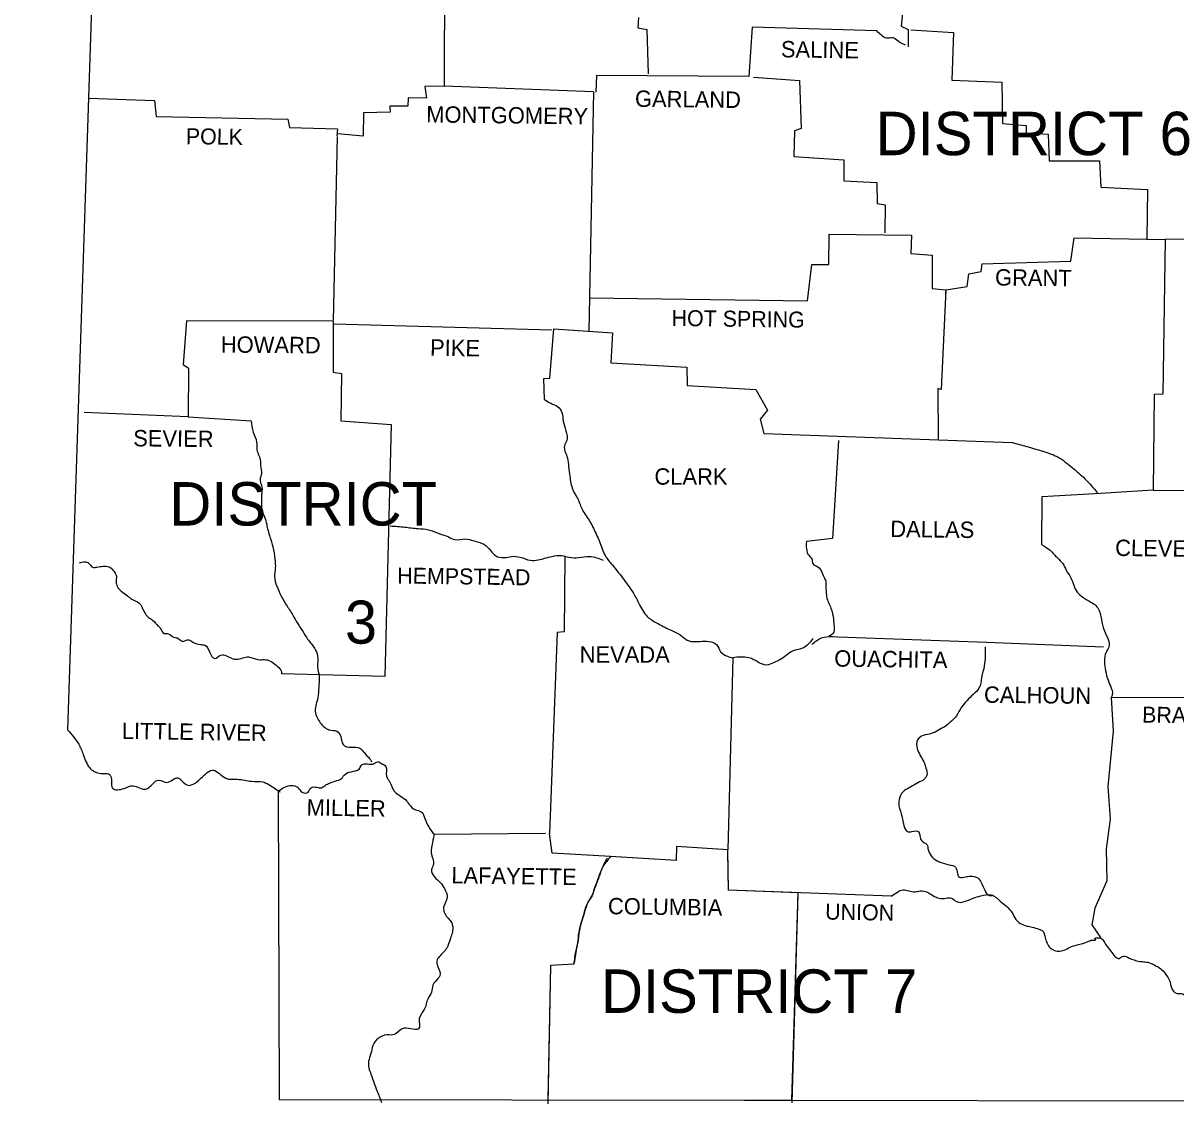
# Model space of a CAD drawing. Extents: x 61396 to 64680, y 55472 to 57605.
# Drawn here: x 63656.7 to 64110.6, y 56565.2 to 56990.7 of the extents above; entities that cross this region are included whole.
import ezdxf

# ---------------------------------------------------------------- set-up
doc = ezdxf.new("R2010")
doc.units = 0
doc.layers.add('Default', color=7, linetype='Continuous')
doc.layers.add('R_Draft', color=7, linetype='Continuous')

msp = doc.modelspace()

# ---------------------------------------------------------------- linework, layer by layer
at = {"layer": 'Default'}
msp.add_line((63881.29, 56963.56), (63879.55, 56869.36), dxfattribs=at)
for points in [[(63656.74, 57368.71), (63687.79, 57119.41), (63674.29, 56712.46)], [(63904.24, 57094.06), (63903.64, 57072.46), (63869.44, 57072.31), (63864.94, 57068.41), (63862.39, 57062.41), (63858.64, 57062.71), (63858.49, 57059.26), (63854.14, 57058.81), (63854.29, 57055.66), (63832.54, 57056.26), (63831.79, 57053.86), (63822.79, 57053.56), (63822.49, 56966.02)], [(64052.59, 57010.51), (64041.79, 57011.71), (64042.24, 57007.66), (64022.59, 57006.91), (64021.99, 57001.06), (64003.54, 57000.01), (64002.49, 56989.51), (64005.19, 56988.16), (64005.19, 56981.26)], [(63898.99, 56992.81), (63898.84, 56988.76), (63902.29, 56988.16), (63902.89, 56970.76)], [(63992.89, 56987.56), (63943.84, 56989.06), (63942.49, 56969.71), (63882.49, 56970.01), (63882.25, 56963.52)], [(64006.24, 56988.01), (64023.04, 56986.96), (64022.44, 56968.21), (64042.09, 56967.46), (64042.39, 56951.11), (64051.69, 56950.36), (64051.69, 56947.51), (64060.39, 56946.91), (64060.69, 56936.41), (64080.49, 56936.41), (64081.09, 56926.06), (64099.39, 56925.16), (64099.24, 56905.66)], [(63822.49, 56966.02), (63822.49, 56965.81), (63814.99, 56965.66), (63815.59, 56961.16), (63808.39, 56961.31), (63808.24, 56958.01), (63801.19, 56958.01), (63801.34, 56955.61), (63790.84, 56955.31), (63790.69, 56946.16), (63780.5, 56947.06)], [(63881.29, 56963.56), (63822.49, 56965.81)], [(63944.29, 56969.41), (63962.44, 56968.06), (63963.04, 56949.16), (63960.49, 56948.26), (63960.19, 56938.21), (63979.84, 56936.86), (63979.84, 56928.61), (63992.89, 56927.86), (63993.04, 56919.61), (63996.19, 56919.16), (63996.04, 56908.06)], [(63682.54, 56961.16), (63708.49, 56960.26), (63709.09, 56953.96), (63760.99, 56952.91), (63761.59, 56949.61), (63780.49, 56949.01), (63780.34, 56946.16)], [(63780.47, 56945.89), (63778.85, 56873.56)], [(64278.19, 56922.91), (64221.49, 56924.41), (64221.19, 56905.96), (64106.44, 56905.51)], [(63879.79, 56882.56), (63965.59, 56881.36), (63967.24, 56895.61), (63973.99, 56895.61), (63974.14, 56907.61), (64006.54, 56907.16), (64006.24, 56899.96), (64014.64, 56899.36), (64014.64, 56886.16), (64020.04, 56885.71), (64019.98, 56884.34)], [(64020.04, 56885.71), (64028.44, 56886.91), (64029.04, 56892.01), (64033.99, 56892.91), (64034.29, 56895.91), (64069.24, 56896.96), (64070.59, 56906.11), (64106.44, 56905.51)], [(64106.44, 56905.51), (64105.54, 56844.61), (64102.09, 56844.46), (64101.64, 56806.81)], [(64020.04, 56885.71), (64018.24, 56846.41), (64016.89, 56846.86), (64017.04, 56826.46)], [(63778.69, 56873.26), (63721.09, 56873.41), (63719.74, 56856.31), (63721.84, 56854.81), (63721.69, 56835.61), (63680.74, 56837.41)], [(63778.84, 56873.26), (63778.84, 56853.31), (63782.14, 56852.71), (63781.84, 56834.11), (63801.64, 56832.61), (63799.24, 56733.46), (63758.44, 56734.51)], [(63779.14, 56872.21), (63864.94, 56869.96)], [(63862.09, 56842.51), (63861.79, 56850.76), (63864.19, 56850.91), (63865.69, 56870.26), (63888.79, 56868.76), (63888.19, 56856.91), (63918.04, 56855.26), (63918.19, 56848.06), (63945.19, 56846.41), (63949.84, 56838.31), (63946.99, 56834.71), (63948.34, 56829.16), (64046.14, 56825.56)], [(63721.69, 56835.61), (63746.59, 56834.11)], [(63977.74, 56826.31), (63975.49, 56787.76), (63965.14, 56786.56)], [(64101.64, 56806.81), (64080.89, 56805.53)], [(64101.64, 56806.81), (64154.74, 56806.51)], [(64080.89, 56805.53), (64057.84, 56804.11), (64057.69, 56785.36)], [(63870.04, 56780.86), (63869.74, 56751.01), (63867.04, 56750.71), (63864.04, 56671.66)], [(63973.99, 56749.21), (64036.09, 56746.96), (64082.14, 56745.16)], [(63936.19, 56740.81), (63934.24, 56665.21), (63913.99, 56666.56), (63913.84, 56661.01), (63885.84, 56662.65)], [(64085.14, 56725.21), (64085.99, 56711.85), (64083.79, 56690.13), (64084.73, 56677.23), (64083.16, 56665.58), (64083.47, 56652.99), (64078.75, 56642.29), (64077.5, 56635.68), (64080.96, 56630.64)], [(64085.14, 56725.21), (64152.94, 56725.36)], [(63757.24, 56688.31), (63757.54, 56566.96), (64307.29, 56566.06)], [(63862.37, 56671.64), (63818.59, 56671.21)], [(63885.84, 56662.65), (63865.09, 56663.86), (63864.04, 56671.66)], [(63998.59, 56646.91), (63934.54, 56649.31), (63934.24, 56664.46)], [(63961.84, 56647.96), (63959.44, 56565.61)], [(63873.64, 56620.21), (63864.34, 56619.61), (63863.29, 56565.16)]]:
    msp.add_lwpolyline(points, dxfattribs=at)
for points in [[(64004.14, 56982.01), (64001.29, 56983.51), (63999.04, 56984.86), (63996.64, 56984.71), (63994.69, 56985.91), (63992.89, 56987.56)], [(63862.09, 56842.51), (63864.49, 56841.01), (63867.34, 56839.66), (63868.84, 56837.41), (63869.44, 56833.96), (63870.49, 56830.21), (63870.79, 56826.31), (63869.89, 56824.21), (63871.09, 56819.41), (63871.54, 56816.11), (63871.99, 56812.21), (63873.19, 56806.96), (63875.14, 56803.36), (63876.94, 56799.01), (63879.94, 56794.36), (63882.49, 56789.26), (63883.69, 56786.56), (63885.94, 56781.01), (63888.79, 56777.26), (63893.29, 56771.56), (63897.34, 56765.71), (63899.59, 56761.36), (63903.04, 56756.56), (63906.94, 56754.16), (63911.89, 56751.61), (63915.04, 56750.11), (63918.64, 56747.56), (63923.29, 56747.26), (63926.74, 56747.26), (63929.89, 56745.91), (63931.39, 56743.21), (63934.09, 56741.41), (63936.19, 56740.81)], [(63746.59, 56834.11), (63747.34, 56829.61), (63748.69, 56825.71), (63748.84, 56822.71), (63750.19, 56818.21), (63750.19, 56816.56), (63750.64, 56813.26), (63750.04, 56811.46), (63750.79, 56807.86), (63750.64, 56805.16), (63750.64, 56802.91), (63750.79, 56799.16), (63751.99, 56795.86), (63753.19, 56790.91), (63753.94, 56788.36), (63755.14, 56784.46), (63755.89, 56779.66), (63756.04, 56776.06), (63755.74, 56772.76), (63756.64, 56769.01), (63758.29, 56765.26), (63760.39, 56761.66), (63762.94, 56757.61), (63764.74, 56754.46), (63766.99, 56751.01), (63768.79, 56748.16), (63771.49, 56744.56), (63772.69, 56741.56), (63772.69, 56737.36), (63773.29, 56733.46), (63773.14, 56729.11), (63772.84, 56725.21), (63771.79, 56719.81), (63772.54, 56717.26), (63775.39, 56713.51), (63777.19, 56712.46), (63780.34, 56711.86), (63781.84, 56709.76), (63782.74, 56706.61), (63785.89, 56705.56), (63789.34, 56705.26), (63790.99, 56703.46), (63793.24, 56701.06), (63793.99, 56699.86)], [(64046.14, 56825.56), (64057.84, 56822.26), (64063.84, 56820.01), (64069.84, 56815.66), (64074.79, 56811.31), (64079.74, 56805.76)], [(63801.34, 56792.71), (63807.04, 56792.26), (63812.29, 56791.66), (63816.34, 56791.21), (63820.54, 56789.71), (63824.29, 56788.36), (63826.69, 56787.31), (63830.74, 56787.61), (63834.19, 56786.86), (63838.09, 56785.51), (63840.94, 56782.96), (63842.74, 56781.01), (63846.19, 56780.26), (63849.04, 56780.71), (63852.49, 56780.41), (63856.39, 56779.21), (63859.54, 56779.36), (63862.09, 56779.96), (63865.09, 56780.71), (63868.84, 56781.01), (63871.69, 56780.41), (63875.44, 56780.26), (63879.79, 56780.71), (63885.19, 56779.21)], [(63965.14, 56786.56), (63965.14, 56783.71), (63966.19, 56781.01), (63967.24, 56779.81), (63967.69, 56777.86), (63969.04, 56776.96), (63970.99, 56775.16), (63972.04, 56772.61), (63972.79, 56770.96), (63972.79, 56768.86), (63972.94, 56766.76), (63973.24, 56764.21), (63975.04, 56759.71), (63975.49, 56757.91), (63975.79, 56756.41), (63975.94, 56753.86), (63975.94, 56750.86), (63973.99, 56749.21)], [(64057.69, 56785.36), (64061.14, 56783.11), (64063.99, 56780.11), (64066.09, 56777.86), (64067.44, 56775.31), (64069.24, 56772.31), (64071.79, 56766.61), (64074.04, 56764.66), (64077.19, 56762.71), (64079.14, 56761.36), (64081.09, 56757.01), (64081.99, 56752.66), (64083.64, 56748.76), (64084.39, 56745.76), (64083.04, 56742.76), (64082.74, 56736.76), (64083.64, 56732.71), (64084.84, 56729.71), (64085.59, 56726.26), (64085.14, 56725.21)], [(63678.94, 56778.16), (63682.24, 56778.31), (63684.49, 56776.36), (63685.84, 56776.51), (63688.24, 56776.81), (63690.49, 56776.66), (63692.14, 56775.31), (63693.49, 56772.91), (63693.34, 56770.66), (63693.49, 56769.76), (63694.54, 56767.81), (63696.34, 56766.31), (63698.29, 56764.81), (63700.09, 56763.61), (63703.09, 56761.66), (63703.39, 56761.06), (63704.59, 56758.66), (63706.09, 56756.71), (63707.89, 56755.51), (63709.84, 56753.41), (63710.74, 56752.51), (63712.24, 56750.41), (63713.89, 56750.26), (63716.14, 56748.91), (63717.79, 56748.46), (63719.59, 56747.26), (63721.39, 56747.86), (63723.64, 56746.96), (63726.64, 56746.06), (63728.29, 56745.76), (63730.24, 56742.91), (63732.19, 56740.51), (63734.59, 56741.86), (63739.09, 56740.51), (63741.94, 56740.36), (63744.49, 56741.11), (63746.44, 56740.96), (63750.04, 56740.06), (63752.29, 56740.06), (63754.69, 56739.16), (63756.94, 56737.36), (63758.44, 56735.41), (63758.44, 56734.51)], [(63967.84, 56748.46), (63966.19, 56746.51), (63964.24, 56744.86), (63961.99, 56744.11), (63959.89, 56743.51), (63957.19, 56741.71), (63955.09, 56740.21), (63952.24, 56738.86), (63949.54, 56737.96), (63946.24, 56739.01), (63944.44, 56740.06), (63942.49, 56740.81), (63936.19, 56740.81)], [(63967.24, 56746.06), (63971.14, 56748.61), (63975.49, 56749.21)], [(64035.49, 56745.16), (64035.19, 56737.66), (64034.14, 56733.01), (64033.09, 56728.81), (64030.84, 56726.41), (64028.44, 56724.01), (64026.19, 56721.31), (64024.24, 56718.01), (64022.29, 56715.91), (64019.74, 56713.81), (64017.19, 56712.31), (64014.34, 56710.96), (64011.19, 56710.21), (64008.94, 56708.56), (64008.79, 56704.96), (64011.34, 56699.86), (64012.24, 56697.46), (64012.54, 56694.61), (64011.49, 56692.96), (64009.09, 56691.61), (64006.24, 56689.96), (64003.69, 56688.46), (64001.89, 56685.91), (64001.59, 56682.46), (64002.79, 56678.41), (64003.24, 56676.01), (64005.19, 56672.26), (64006.69, 56672.41), (64009.39, 56672.26), (64009.69, 56671.51), (64009.84, 56670.76), (64010.44, 56668.81), (64012.69, 56667.16), (64012.99, 56665.66), (64014.34, 56662.81), (64016.59, 56660.86), (64018.24, 56660.26), (64021.69, 56659.21), (64023.49, 56658.76), (64025.44, 56654.41), (64027.84, 56654.56), (64029.64, 56654.86), (64032.64, 56654.11), (64033.99, 56652.31), (64035.34, 56649.31), (64037.14, 56647.21), (64038.34, 56647.21)], [(63674.29, 56712.46), (63678.64, 56706.76), (63680.44, 56702.71), (63682.99, 56697.46), (63686.74, 56695.36), (63691.09, 56694.61), (63691.99, 56689.51), (63696.49, 56689.36), (63700.09, 56690.41), (63705.04, 56689.06), (63710.29, 56692.66), (63713.29, 56691.76), (63717.64, 56693.56), (63720.94, 56690.86), (63726.64, 56693.26), (63731.74, 56696.56), (63736.54, 56693.41), (63741.19, 56692.96), (63746.74, 56692.21), (63751.09, 56691.91), (63754.99, 56689.96), (63757.84, 56688.01), (63757.24, 56688.31)], [(63757.24, 56688.31), (63762.49, 56690.56), (63764.74, 56689.81), (63766.69, 56687.86), (63768.94, 56687.86), (63770.14, 56689.66), (63772.39, 56689.81), (63774.19, 56689.66), (63776.14, 56690.86), (63777.79, 56691.61), (63780.04, 56692.36), (63781.69, 56692.96), (63783.19, 56694.61), (63785.89, 56695.96), (63789.04, 56697.01), (63789.94, 56698.51), (63791.44, 56699.11), (63794.44, 56698.96), (63796.39, 56699.86), (63798.04, 56699.11), (63799.54, 56698.06), (63799.84, 56694.16), (63801.04, 56692.06), (63802.84, 56688.31), (63805.39, 56686.36), (63807.79, 56684.41), (63808.69, 56683.21), (63811.24, 56680.96), (63813.49, 56680.21), (63814.54, 56678.56), (63816.19, 56674.66), (63818.59, 56671.21)], [(63818.59, 56671.21), (63817.69, 56666.86), (63817.54, 56663.41), (63818.29, 56659.36), (63817.54, 56657.41), (63818.74, 56654.56), (63820.99, 56652.31), (63822.64, 56649.91), (63823.69, 56646.46), (63822.34, 56642.56), (63823.84, 56638.51), (63825.19, 56637.01), (63825.94, 56634.61), (63824.89, 56629.96), (63823.54, 56626.51), (63820.54, 56623.06), (63819.64, 56621.41), (63820.09, 56619.16), (63820.84, 56615.56), (63820.09, 56614.51), (63818.14, 56611.96), (63817.54, 56609.11), (63816.19, 56606.71), (63814.69, 56602.36), (63812.74, 56598.76), (63812.44, 56594.71), (63809.44, 56594.71), (63805.99, 56594.71), (63802.84, 56592.46), (63799.99, 56592.31), (63796.54, 56590.96), (63794.44, 56588.11), (63793.69, 56584.96), (63792.79, 56581.96), (63793.69, 56576.86), (63795.04, 56573.26), (63796.09, 56570.41), (63797.89, 56565.76)], [(63873.64, 56620.21), (63874.39, 56625.01), (63875.14, 56628.76), (63875.59, 56632.36), (63876.49, 56636.41), (63877.84, 56640.76), (63879.04, 56644.36), (63880.69, 56646.91), (63881.74, 56649.91), (63883.09, 56653.51), (63884.44, 56657.26), (63886.84, 56662.06)], [(63998.59, 56646.91), (64000.99, 56648.56), (64003.24, 56649.46), (64005.49, 56649.01), (64007.89, 56648.71), (64009.99, 56649.01), (64012.69, 56648.56), (64014.94, 56647.21), (64017.49, 56646.16), (64020.04, 56646.16), (64022.29, 56646.16), (64024.24, 56644.81), (64027.84, 56644.96), (64030.84, 56646.16), (64033.84, 56647.06), (64037.89, 56647.51), (64041.49, 56644.96), (64044.04, 56642.86), (64046.14, 56640.46), (64047.64, 56637.76), (64049.29, 56636.26), (64051.99, 56635.21), (64054.09, 56634.76), (64056.64, 56634.01), (64057.99, 56633.41), (64059.19, 56630.56), (64061.14, 56626.66), (64064.89, 56625.31), (64069.54, 56627.11), (64073.29, 56628.16), (64075.99, 56629.06), (64077.64, 56629.66), (64079.14, 56629.81), (64078.69, 56630.11), (64080.49, 56630.56), (64082.14, 56629.36), (64083.19, 56627.71), (64084.99, 56625.31), (64086.64, 56623.21), (64088.29, 56622.46), (64089.94, 56623.36), (64092.19, 56622.61), (64094.14, 56621.86), (64096.39, 56621.26), (64098.34, 56621.11), (64100.89, 56620.51), (64102.84, 56619.46), (64104.64, 56618.41), (64106.44, 56616.46), (64108.24, 56613.46), (64108.84, 56611.06), (64110.94, 56608.66), (64112.89, 56608.66), (64115.74, 56604.76), (64116.79, 56603.26), (64119.04, 56600.56), (64120.69, 56600.56), (64123.84, 56599.96)]]:
    msp.add_spline(points, degree=3, dxfattribs=at)
at = {"layer": 'R_Draft'}
for p, q in [((63959.47, 56566.63), (63961.85, 56648.29)), ((63863.32, 56566.79), (63959.47, 56566.63))]:
    msp.add_line(p, q, dxfattribs=at)
for points in [[(63934.24, 56665.21), (63913.99, 56666.56), (63913.84, 56661.01), (63888.04, 56662.52)], [(63961.85, 56648.29), (63934.54, 56649.31), (63934.24, 56665.21)], [(63873.64, 56620.21), (63864.34, 56619.61), (63863.32, 56566.79)]]:
    msp.add_lwpolyline(points, dxfattribs=at)
msp.add_spline([(63888.04, 56662.52), (63887.05, 56661.3), (63886.04, 56660.02), (63885.12, 56658.67), (63884.44, 56657.26), (63883.77, 56655.38), (63883.09, 56653.51), (63881.74, 56649.91), (63881.47, 56649.16), (63881.22, 56648.41), (63880.96, 56647.66), (63880.69, 56646.91), (63880.53, 56646.57), (63880.33, 56646.24), (63879.86, 56645.64), (63879.39, 56645.03), (63879.2, 56644.7), (63879.04, 56644.36), (63877.84, 56640.76), (63876.49, 56636.41), (63875.59, 56632.36), (63875.46, 56631.46), (63875.37, 56630.56), (63875.27, 56629.66), (63875.14, 56628.76), (63874.96, 56627.82), (63874.76, 56626.89), (63874.56, 56625.95), (63874.39, 56625.01), (63873.64, 56620.21)], degree=3, dxfattribs=at)

# ---------------------------------------------------------------- texts
at = {"layer": 'Default'}
for s, height, rotation, p in [('SALINE', 6.451, 359.1491, (63955.09, 56977.21)), ('GARLAND', 6.451, 359.3658, (63897.64, 56957.71)), ('MONTGOMERY', 6.451, 359.2944, (63815.44, 56951.56)), ('POLK', 6.299, 359.2152, (63720.79, 56943.01)), ('GRANT', 6.451, 359.4032, (64039.39, 56887.36)), ('HOT SPRING', 6.301, 359.2216, (63912.04, 56871.46)), ('HOWARD', 6.451, 359.5145, (63734.59, 56860.96)), ('PIKE', 6.449, 359.0452, (63816.94, 56859.76)), ('SEVIER', 6.451, 359.4271, (63700.09, 56824.06)), ('DALLAS', 6.449, 359.2462, (63998.14, 56788.37)), ('CLEVELAND', 6.451, 359.3376, (64086.68, 56780.9)), ('HEMPSTEAD', 6.299, 359.1885, (63804.04, 56770.06)), ('OUACHITA', 6.451, 359.2043, (63976.09, 56737.36)), ('CALHOUN', 6.451, 359.3634, (64035.04, 56723.11)), ('BRADLEY', 6.299, 359.1449, (64097.29, 56715.31)), ('LITTLE RIVER', 6.451, 359.1697, (63695.59, 56708.86)), ('MILLER', 6.449, 359.1319, (63768.34, 56678.71)), ('LAFAYETTE', 6.449, 359.1839, (63825.34, 56652.01)), ('COLUMBIA', 6.449, 359.2125, (63886.99, 56639.86)), ('UNION', 6.301, 358.9584, (63972.49, 56637.76))]:
    msp.add_text(s, height=height, rotation=rotation, dxfattribs=at).set_placement(p)
for s, height, p in [('DISTRICT 6', 17.1, (63992.44, 56938.66)), ('CLARK', 6.45, (63905.33, 56808.95)), ('DISTRICT', 17.1, (63714.34, 56792.86)), ('3', 16.95, (63783.49, 56746.36)), ('NEVADA', 6.45, (63875.89, 56738.86)), ('DISTRICT 7', 17.1, (63884.29, 56601.01))]:
    msp.add_text(s, height=height, dxfattribs=at).set_placement(p)

doc.saveas('drawing.dxf')
